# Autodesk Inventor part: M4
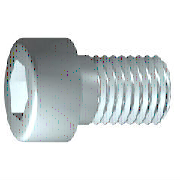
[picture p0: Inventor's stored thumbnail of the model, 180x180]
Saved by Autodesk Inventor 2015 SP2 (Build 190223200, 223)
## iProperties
IsCustomPart: 0
Company: 한국ATC센터
Created: 2014-10
Part Number: M4
Material: 강철
Description: 6각머리 태핑 나사
Document SubType Name: Modeling
Standard: KS B 1003
Designer: KYOUNG IL JANG
Standards Organization: KS
Language: ko-KR
Size Designation: M 4 x 10
Categories: <MemberInstance><Categories><Category DisplayName="조임쇠" InternalName="e4da775c-781d-43d5-af7c-5136215cf5a6" Mnemonic="FSTN"><Category DisplayName="볼트" InternalN
Density: 7.85 g/cm^3
Mass: 2.03451 g
Surface Area: 3.0572 cm^2
Volume: 0.259174 cm^3
Appearance: 검은색 캐스트
Author: KYOUNG IL JANG
Revision Number: 1
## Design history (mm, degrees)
sketch "스케치1"
  geometry: L1 (-1, 0)-(10, 0); L2 (10, 0)-(10, 2); L3 (10, 2)-(1.75, 2); L4 (1.75, 2)-(1.32, 2); L5 (1.32, 2)-(0, 2); L6 (0, 2)-(0, 3.5); L7 (0, 3.5)-(-4, 3.5); L8 (-4, 3.5)-(-4, 1.732); L9 (-4, 1.732)-(-2, 1.732); L10 (-2, 1.732)-(-1, 0); L11 (-6.8, 0)-(12.8, 0) reference; L12 (0, -0.7)-(0, 4.2) reference; L13 (1.75, 2)-(0, 2)
  constraints: 22 end point, 6 parallel, 2 collinear, 2 perpendicular, 1 horizontal, 1 point on line
  dimensions: "d1" = 8.25 distance from line of L3.end L2 (= GEL); "d2" = 0.42952 distance of L4.end L3.end (computed from GAL); "d3" = 4 distance between parallel lines of L8 L6 (= KOH); "d4" = 2 distance of L8.end L9.end (= INTI); "d5" = 60 deg angle of L10 L1; "d6" = 4 diameter of L3 L1 (= GD); "d7" = 4 diameter of L5 L1 (= BDM); "d8" = 3.4641 diameter of L9 L1 (= 1.1547 x SW); "d9" = 7 diameter of L7 L1 (= KOD); "d26" = 10 distance between parallel lines of L12 L2 (= NLG)
revolve "본체" sketch "스케치1" stored, may be unused: angle "d10" = 90 deg
sketch "스케치2"
  geometry: L1 (0, -4.9)-(0, 4.9) reference; L2 (-4.9, 0)-(4.9, 0) reference; L3 (1.732, 0)-(0.866, -1.5); L4 (0.866, -1.5)-(-0.866, -1.5); L5 (-0.866, -1.5)-(-1.732, 0); L6 (-1.732, 0)-(-0.866, 1.5); L7 (-0.866, 1.5)-(0.866, 1.5); L8 (0.866, 1.5)-(1.732, 0); 2 further points
  constraints: 12 end point, 1 coincident, 1 horizontal alignment, 1 point on line, 12 other
extrude "슬롯" join sketch "스케치2" stored distance "d11" = 10; taper "d12" = 0 deg
workplane "Work Plane1"
fillet "Fillet2" dims "d30" = 0.1 (= R)
body "Solid1"
fillet "모깎기1" dims "d17" = 0.4 (= RR)
feature "스레드" dims "d13" = 8.25 (= GEL), "d14" = 0
chamfer "모따기1" distance "d15" = 0.42941 (= -0.5 x SPD + 0.5 x GD); stored, may be unused: second distance "d16" = 0.42941 (= GUL), angle "d27" = 45 deg
other parameters: "GD" = 4 (= NND) [user parameter; used in 2 equation terms], "NLG" = 10 [user parameter; used in 1 equation term], "GEL" = 8.25 [user parameter; used in 2 equation terms], "KOD" = 7 [user parameter; used in 1 equation term], "KOH" = 4 [user parameter; used in 1 equation term], "INTI" = 2 [user parameter; used in 1 equation term], "GAL" = 0.42941 (= 0.61345 x PTC) [user parameter; used in 1 equation term], "GUL" = 0.42941 (= 0.61345 x PTC) [user parameter; used in 1 equation term], "BDM" = 4 (= NND) [user parameter; used in 1 equation term], "SW" = 3 [user parameter; used in 2 equation terms], "RR" = 0.4 [user parameter; used in 1 equation term], "SPD" = 3.14117 (= NND - 1.2269 x PTC) [user parameter; used in 1 equation term], "d19" = 0, "d28" = 0, "d29" = 0, "R" = 0.1 [user parameter; used in 1 equation term], "PHH" = 0.2 [user parameter], "GD1" = 3.14117 (= THREADDIA - 1.2269 x PTC) [user parameter], "THREADDIA" = 4 [user parameter; used in 1 equation term], "FAWI" = 45 deg [user parameter], "TPU" = 14.28571 (computed from PTC) [user parameter], "PTC" = 0.7 [user parameter; used in 5 equation terms], "NND" = 4 [user parameter; used in 3 equation terms], "TOA" = 30 deg [user parameter], "E0" = 3.465 (= 1.155 x SW) [user parameter]
